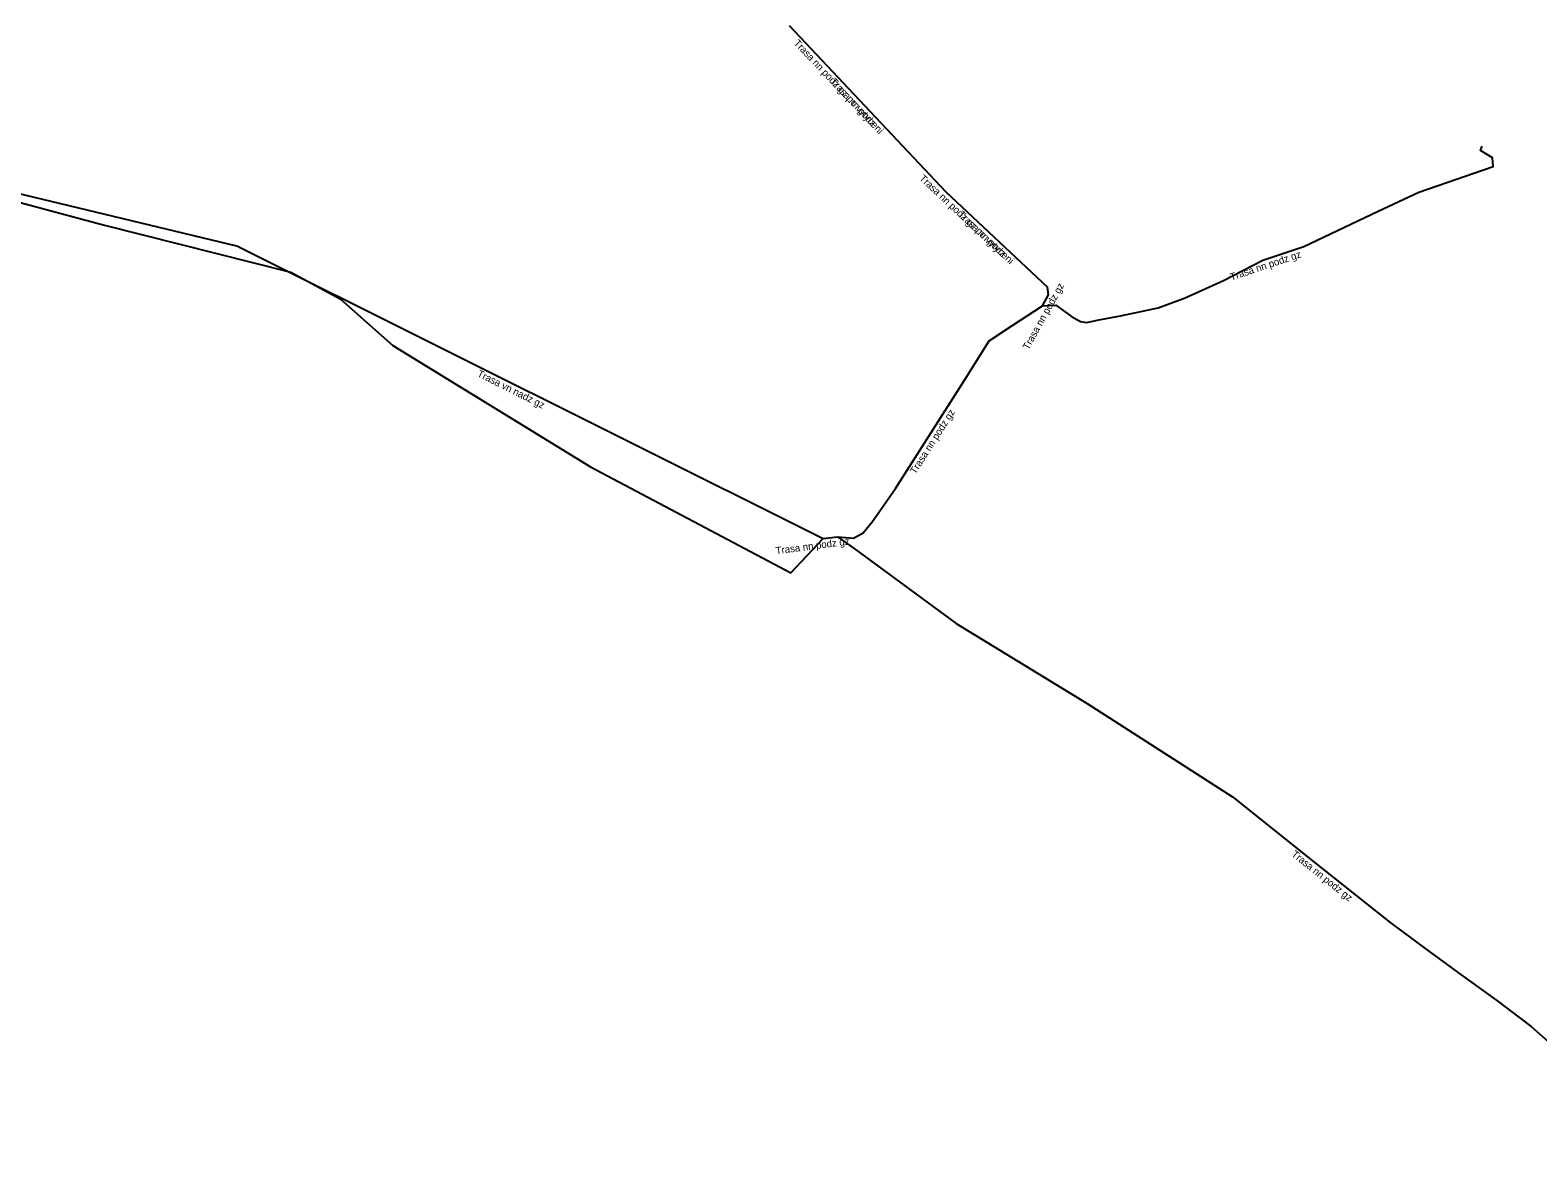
# Model space of a CAD drawing. Extents: x -666920 to -666608, y -1105526 to -1105233.
# Drawn here: x -666865.4 to -666760.5, y -1105525.7 to -1105447.2 of the extents above; entities that cross this region are included whole.
import ezdxf

# ---------------------------------------------------------------- set-up
doc = ezdxf.new("R2010")
doc.units = 0
for name, color, linetype in [('Popiskový text - Ostatní atributy Trasy', 7, 'Continuous'), ('Spojnice NN', 7, 'Continuous'), ('Spojnice VN', 7, 'Continuous')]:
    doc.layers.add(name, color=color, linetype=linetype)

msp = doc.modelspace()

# ---------------------------------------------------------------- linework, layer by layer
at = {"layer": 'Spojnice NN'}
for points in [[(-666812.6, -1105446.89), (-666801.69, -1105458.45)], [(-666812.6, -1105446.89), (-666801.69, -1105458.45)], [(-666794.98, -1105466.38), (-666794.04, -1105466.34), (-666792.95, -1105467.11), (-666792.33, -1105467.46), (-666791.89, -1105467.53), (-666791.17, -1105467.38), (-666789.54, -1105467.07), (-666786.94, -1105466.52), (-666785.05, -1105465.81), (-666782.38, -1105464.62), (-666779.65, -1105463.21), (-666776.81, -1105462.26), (-666771.62, -1105459.79), (-666768.8, -1105458.48), (-666763.64, -1105456.69), (-666763.68, -1105456.09), (-666764.52, -1105455.57), (-666764.39, -1105455.27)], [(-666871.62, -1105457.72), (-666860.22, -1105460.76), (-666847.25, -1105464.03), (-666843.83, -1105465.88), (-666840.15, -1105469.14), (-666826.41, -1105477.57), (-666812.49, -1105484.94), (-666810.22, -1105482.56)], [(-666801.69, -1105458.45), (-666794.62, -1105465.08)], [(-666801.69, -1105458.45), (-666794.62, -1105465.08)], [(-666794.98, -1105466.38), (-666794.56, -1105465.62), (-666794.62, -1105465.08)], [(-666809.24, -1105482.43), (-666808.13, -1105482.52), (-666807.46, -1105482.16), (-666806.82, -1105481.38), (-666805.19, -1105479.08), (-666800.4, -1105471.54), (-666798.69, -1105468.81), (-666797.05, -1105467.71), (-666794.98, -1105466.38)], [(-666810.22, -1105482.56), (-666809.24, -1105482.43)], [(-666809.24, -1105482.43), (-666808.07, -1105483.24), (-666800.99, -1105488.45), (-666791.87, -1105494.02), (-666781.77, -1105500.51), (-666775.52, -1105505.49), (-666770.8, -1105509.25), (-666768.36, -1105511.05), (-666765.85, -1105512.87), (-666763.38, -1105514.66), (-666760.98, -1105516.48), (-666756.44, -1105520.49), (-666751.69, -1105525.63), (-666751.1, -1105525.67), (-666741.41, -1105518.15)]]:
    msp.add_lwpolyline(points, dxfattribs=at)
at = {"layer": 'Spojnice VN'}
for points in [[(-666850.92, -1105462.25), (-666912.12, -1105447.54)], [(-666850.92, -1105462.25), (-666810.22, -1105482.56)]]:
    msp.add_lwpolyline(points, dxfattribs=at)

# ---------------------------------------------------------------- texts
at = {"layer": 'Popiskový text - Ostatní atributy Trasy'}
for s, rotation, p in [('Trasa nn podz gz po vytyceni', 313.343, (-666812.31, -1105448.15)), ('Trasa nn podz', 313.343, (-666809.78, -1105450.83)), ('Trasa nn podz gz po vytyceni', 316.8395, (-666803.58, -1105457.57)), ('Trasa nn podz', 316.8395, (-666800.9, -1105460.09)), ('Trasa nn podz gz', 18.4955, (-666781.84, -1105464.63)), ('Trasa nn podz gz', 61.0736, (-666795.95, -1105469.48)), ('Trasa vn nadz gz', 333.48, (-666834.34, -1105471.25)), ('Trasa nn podz gz', 57.5731, (-666803.81, -1105478.12)), ('Trasa nn podz gz', 7.5563, (-666813.5, -1105483.65)), ('Trasa nn podz gz', 321.4588, (-666777.7, -1105504.58))]:
    msp.add_text(s, height=0.5, rotation=rotation, dxfattribs=at).set_placement(p)

doc.saveas('drawing.dxf')
